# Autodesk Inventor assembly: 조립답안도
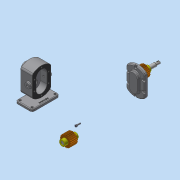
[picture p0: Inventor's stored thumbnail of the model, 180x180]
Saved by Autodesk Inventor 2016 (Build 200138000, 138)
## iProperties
Created: 2019-03
Part Number: 조립답안도
Material: 일반
Document SubType Name: Assembly
Designer: 3sil_cad0123
Author: 3sil_cad0123
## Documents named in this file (11)
- C:\Users\3sil_cad0123\Desktop\490307V1044\조립답안도.iam
- C:\Users\3sil_cad0123\Desktop\490307V1044\본체.ipt
- C:\Users\3sil_cad0123\Desktop\490307V1044\개스킷.ipt
- C:\Users\3sil_cad0123\Desktop\490307V1044\메인축.ipt
- C:\Users\3sil_cad0123\Desktop\490307V1044\베어링부시.ipt
- C:\Users\3sil_cad0123\Desktop\490307V1044\볼트 M5.ipt
- C:\Users\3sil_cad0123\Desktop\490307V1044\서브축.ipt
- C:\Users\3sil_cad0123\Desktop\490307V1044\스퍼기어.ipt
- C:\Users\3sil_cad0123\Desktop\490307V1044\오일 실 16 28 7.ipt
- C:\Users\3sil_cad0123\Desktop\490307V1044\커버.ipt
- C:\Users\3sil_cad0123\Desktop\490307V1044\키 6 x 6 x 18.ipt
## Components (1 placed, 1 different names)
1. 개스킷:1
